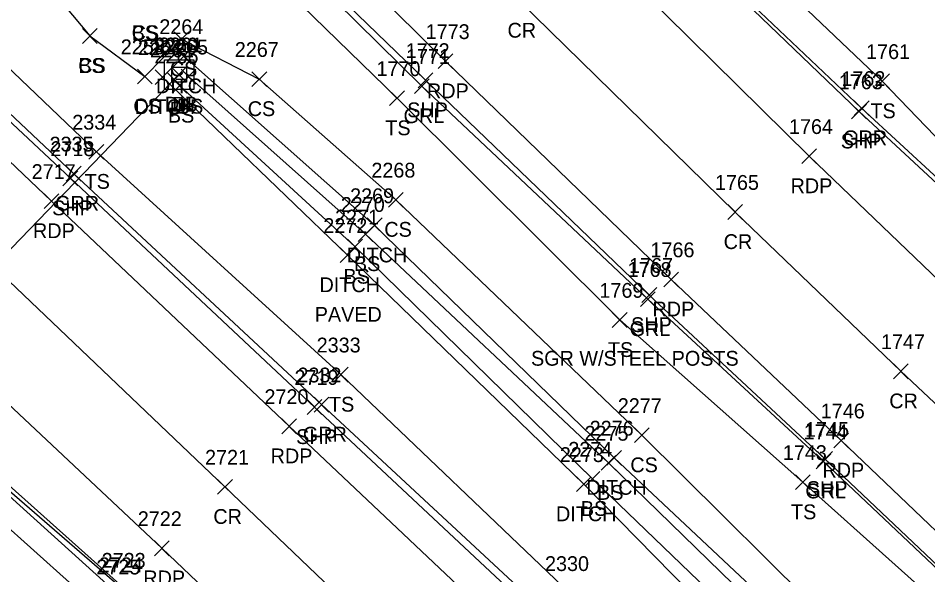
# Model space of a CAD drawing. Extents: x 1647574 to 1652703, y 212895 to 228670.
# Drawn here: x 1648547.8 to 1648670.8, y 227486.1 to 227561.3 of the extents above; entities that cross this region are included whole.
import ezdxf

# ---------------------------------------------------------------- set-up
doc = ezdxf.new("R2010")
doc.units = 0
for name, color, linetype in [('D_A', 7, 'Continuous'), ('D_C', 7, 'Continuous'), ('D_I', 7, 'Continuous'), ('D_TIC', 7, 'Continuous'), ('DCP', 7, 'Continuous'), ('DD', 7, 'Continuous'), ('DS', 7, 'Continuous'), ('L_A', 7, 'Continuous'), ('L_I', 7, 'Continuous'), ('L_TIC', 7, 'Continuous'), ('LELB', 7, 'Continuous'), ('P_A', 7, 'Continuous'), ('P_I', 7, 'Continuous'), ('P_TIC', 7, 'Continuous'), ('PET', 7, 'Continuous'), ('PRC', 7, 'Continuous'), ('PSP', 7, 'Continuous'), ('R_A', 7, 'Continuous'), ('R_C', 7, 'Continuous'), ('R_I', 7, 'Continuous'), ('R_TIC', 7, 'Continuous'), ('RC', 7, 'Continuous'), ('RGR', 7, 'Continuous')]:
    doc.layers.add(name, color=color, linetype=linetype)

msp = doc.modelspace()

# ---------------------------------------------------------------- linework, layer by layer
at = {"layer": 'D_TIC'}
for points in [[(1648569.22, 227555.15), (1648571.22, 227557.15)], [(1648571.22, 227555.15), (1648569.22, 227557.15)], [(1648566.35, 227552.33), (1648568.35, 227554.33)], [(1648568.35, 227552.33), (1648566.35, 227554.33)], [(1648566.35, 227552.33), (1648568.35, 227554.33)], [(1648568.35, 227552.33), (1648566.35, 227554.33)], [(1648568.57, 227552.68), (1648570.57, 227554.68)], [(1648570.57, 227552.68), (1648568.57, 227554.68)], [(1648567.95, 227552.01), (1648569.95, 227554.01)], [(1648569.95, 227552.01), (1648567.95, 227554.01)], [(1648595.04, 227532.3), (1648597.04, 227534.3)], [(1648597.04, 227532.3), (1648595.04, 227534.3)], [(1648591.36, 227528.27), (1648593.36, 227530.27)], [(1648593.36, 227528.27), (1648591.36, 227530.27)], [(1648627.44, 227500.88), (1648629.44, 227502.88)], [(1648629.44, 227500.88), (1648627.44, 227502.88)], [(1648623.34, 227497.31), (1648625.34, 227499.31)], [(1648625.34, 227497.31), (1648623.34, 227499.31)]]:
    msp.add_lwpolyline(points, dxfattribs=at)
at = {"layer": 'DCP'}
msp.add_lwpolyline([(1648568.95, 227553.01), (1648531, 227513.75)], dxfattribs=at)
at = {"layer": 'DD'}
for points in [[(1648567.35, 227553.33), (1648570.22, 227556.15), (1648596.04, 227533.3), (1648628.44, 227501.88), (1648658.02, 227474.12), (1648679.67, 227455.41), (1648690.82, 227447.94), (1648713.45, 227432.44), (1648744.75, 227411.46), (1648774.42, 227388.82), (1648782.61, 227380), (1648760.63, 227395.22), (1648734.75, 227411.81), (1648707.17, 227430.08), (1648688.91, 227442.53), (1648686.08, 227443.55), (1648681.35, 227446.24), (1648682.93, 227440.96), (1648688.01, 227426.23), (1648692.45, 227411.09)], [(1648567.35, 227553.33), (1648592.36, 227529.27), (1648624.34, 227498.31), (1648653.08, 227469.04), (1648672.69, 227449.29), (1648678.63, 227437.2), (1648685.39, 227422.2), (1648683.98, 227419.76)]]:
    msp.add_lwpolyline(points, dxfattribs=at)
at = {"layer": 'DS'}
for p, q in [((1648567.61, 227555.67), (1648571.61, 227555.67)), ((1648567.61, 227551.67), (1648567.61, 227555.67)), ((1648571.61, 227555.67), (1648571.61, 227551.67)), ((1648568.61, 227552.67), (1648568.61, 227554.67)), ((1648568.61, 227554.67), (1648570.61, 227554.67)), ((1648570.61, 227554.67), (1648570.61, 227552.67)), ((1648569.61, 227553.67), (1648569.61, 227553.67)), ((1648569.61, 227553.67), (1648569.61, 227553.67)), ((1648570.61, 227552.67), (1648568.61, 227552.67)), ((1648571.61, 227551.67), (1648567.61, 227551.67))]:
    msp.add_line(p, q, dxfattribs=at)
at = {"layer": 'L_TIC'}
for points in [[(1648556.52, 227557.9), (1648558.52, 227559.9)], [(1648558.52, 227557.9), (1648556.52, 227559.9)], [(1648556.52, 227557.9), (1648558.52, 227559.9)], [(1648558.52, 227557.9), (1648556.52, 227559.9)], [(1648568.91, 227557.45), (1648570.91, 227559.45)], [(1648570.91, 227557.45), (1648568.91, 227559.45)], [(1648563.97, 227552.43), (1648565.97, 227554.43)], [(1648565.97, 227552.43), (1648563.97, 227554.43)], [(1648569.86, 227552.4), (1648571.86, 227554.4)], [(1648571.86, 227552.4), (1648569.86, 227554.4)], [(1648569.86, 227552.4), (1648571.86, 227554.4)], [(1648571.86, 227552.4), (1648569.86, 227554.4)], [(1648568.64, 227551.19), (1648570.64, 227553.19)], [(1648570.64, 227551.19), (1648568.64, 227553.19)], [(1648579.44, 227552.07), (1648581.44, 227554.07)], [(1648581.44, 227552.07), (1648579.44, 227554.07)], [(1648663.68, 227551.78), (1648665.68, 227553.78)], [(1648665.68, 227551.78), (1648663.68, 227553.78)], [(1648598.07, 227549.48), (1648600.07, 227551.48)], [(1648600.07, 227549.48), (1648598.07, 227551.48)], [(1648557.41, 227542.24), (1648559.41, 227544.24)], [(1648559.41, 227542.24), (1648557.41, 227544.24)], [(1648597.91, 227535.76), (1648599.91, 227537.76)], [(1648599.91, 227535.76), (1648597.91, 227537.76)], [(1648593.8, 227531.12), (1648595.8, 227533.12)], [(1648595.8, 227531.12), (1648593.8, 227533.12)], [(1648592.38, 227529.42), (1648594.38, 227531.42)], [(1648594.38, 227529.42), (1648592.38, 227531.42)], [(1648628.18, 227519.51), (1648630.18, 227521.51)], [(1648630.18, 227519.51), (1648628.18, 227521.51)], [(1648590.46, 227512.12), (1648592.46, 227514.12)], [(1648592.46, 227512.12), (1648590.46, 227514.12)], [(1648631.18, 227503.93), (1648633.18, 227505.93)], [(1648633.18, 227503.93), (1648631.18, 227505.93)], [(1648626.68, 227500.2), (1648628.68, 227502.2)], [(1648628.68, 227500.2), (1648626.68, 227502.2)], [(1648624.49, 227498.03), (1648626.49, 227500.03)], [(1648626.49, 227498.03), (1648624.49, 227500.03)], [(1648652.94, 227497.58), (1648654.94, 227499.58)], [(1648654.94, 227497.58), (1648652.94, 227499.58)]]:
    msp.add_lwpolyline(points, dxfattribs=at)
at = {"layer": 'LELB'}
for points in [[(1648003.1, 228082.75), (1648021.4, 228065.95), (1648044.73, 228045.59), (1648079.17, 228018.19), (1648101.81, 227996.84), (1648138.98, 227971.46), (1648165.99, 227945.56), (1648168.81, 227943.47), (1648170.35, 227941.98), (1648172.46, 227939.54), (1648204.47, 227916.76), (1648236.47, 227884.75), (1648262.27, 227857.29), (1648293.8, 227821.06), (1648324.53, 227790.88), (1648359.53, 227760.77), (1648386.88, 227728.2), (1648427.75, 227689.04), (1648461.36, 227653.83), (1648490.92, 227628.14), (1648517.86, 227599.3), (1648549.31, 227568.74), (1648557.52, 227558.9)], [(1648859.74, 227356.65), (1648840.12, 227378.91), (1648802.29, 227415.99), (1648770.94, 227445.62), (1648740.28, 227477.01), (1648708.8, 227506.87), (1648686.01, 227530.68), (1648664.68, 227552.78), (1648630.72, 227585.09), (1648595.33, 227619.93), (1648569.85, 227644.46), (1648530.91, 227681.62), (1648503.48, 227711.09), (1648474.08, 227742.1), (1648442.94, 227774.58), (1648417.61, 227803.67), (1648387.3, 227839.86), (1648354.19, 227879.71), (1648321.73, 227919.78)], [(1648774.58, 227389.56), (1648743.29, 227416.76), (1648711.06, 227445.83), (1648678.9, 227476.26), (1648653.94, 227498.58), (1648629.18, 227520.51), (1648599.07, 227550.48), (1648561.98, 227586.59), (1648537.34, 227611.83), (1648495.7, 227652.57), (1648469.81, 227680.64), (1648438.58, 227713.56), (1648409.77, 227744.99), (1648382.96, 227775.49), (1648351.84, 227812.3), (1648319.03, 227851.85)], [(1648685.39, 227422.2), (1648676.45, 227434.08), (1648654, 227457.48), (1648622.43, 227483.58), (1648591.46, 227513.12), (1648558.41, 227543.24), (1648525.7, 227574.49), (1648490.45, 227607.71), (1648459.18, 227639.73), (1648423.29, 227671.04), (1648396.89, 227698.59), (1648372.2, 227720.93), (1648349.64, 227747.39), (1648318.23, 227770.21)], [(1648324.38, 227700.33), (1648355.95, 227670.04), (1648394.92, 227634.14), (1648428.77, 227603.61), (1648465.67, 227570.17), (1648497.97, 227538.04), (1648525.78, 227510.98), (1648559.61, 227480.7), (1648593.98, 227451.63), (1648632.72, 227416.53), (1648638.02, 227413.49)], [(1648557.52, 227558.9), (1648564.97, 227553.43), (1648569.91, 227558.45), (1648580.44, 227553.07), (1648598.91, 227536.76), (1648632.18, 227504.93), (1648659.98, 227477.37), (1648684.6, 227459.15), (1648697.58, 227453.74)], [(1648570.86, 227553.4), (1648569.64, 227552.19), (1648593.38, 227530.42), (1648625.49, 227499.03), (1648654.22, 227471.4), (1648675.13, 227451.27), (1648677.2, 227452.71), (1648687.88, 227445.25), (1648711.27, 227429.65), (1648742.96, 227408.64)], [(1648570.86, 227553.4), (1648594.8, 227532.12), (1648627.68, 227501.2), (1648656.32, 227473.31), (1648678.08, 227454.03), (1648689.55, 227446.73), (1648712.67, 227431.2), (1648742.96, 227408.64), (1648773.62, 227388.35)]]:
    msp.add_lwpolyline(points, dxfattribs=at)
at = {"layer": 'P_TIC'}
for points in [[(1648604.63, 227554.48), (1648606.63, 227556.48)], [(1648606.63, 227554.48), (1648604.63, 227556.48)], [(1648601.92, 227551.91), (1648603.92, 227553.91)], [(1648603.92, 227551.91), (1648601.92, 227553.91)], [(1648660.55, 227547.7), (1648662.55, 227549.7)], [(1648662.55, 227547.7), (1648660.55, 227549.7)], [(1648653.81, 227541.65), (1648655.81, 227543.65)], [(1648655.81, 227541.65), (1648653.81, 227543.65)], [(1648553.89, 227538.66), (1648555.89, 227540.66)], [(1648555.89, 227538.66), (1648553.89, 227540.66)], [(1648551.35, 227535.57), (1648553.35, 227537.57)], [(1648553.35, 227535.57), (1648551.35, 227537.57)], [(1648643.8, 227534.1), (1648645.8, 227536.1)], [(1648645.8, 227534.1), (1648643.8, 227536.1)], [(1648635.13, 227524.99), (1648637.13, 227526.99)], [(1648637.13, 227524.99), (1648635.13, 227526.99)], [(1648632.18, 227522.88), (1648634.18, 227524.88)], [(1648634.18, 227522.88), (1648632.18, 227524.88)], [(1648666.2, 227512.57), (1648668.2, 227514.57)], [(1648668.2, 227512.57), (1648666.2, 227514.57)], [(1648586.9, 227507.74), (1648588.9, 227509.74)], [(1648588.9, 227507.74), (1648586.9, 227509.74)], [(1648583.49, 227505.14), (1648585.49, 227507.14)], [(1648585.49, 227505.14), (1648583.49, 227507.14)], [(1648658.12, 227503.21), (1648660.12, 227505.21)], [(1648660.12, 227503.21), (1648658.12, 227505.21)], [(1648655.94, 227500.72), (1648657.94, 227502.72)], [(1648657.94, 227500.72), (1648655.94, 227502.72)], [(1648574.8, 227496.95), (1648576.8, 227498.95)], [(1648576.8, 227496.95), (1648574.8, 227498.95)], [(1648566.27, 227488.65), (1648568.27, 227490.65)], [(1648568.27, 227488.65), (1648566.27, 227490.65)]]:
    msp.add_lwpolyline(points, dxfattribs=at)
at = {"layer": 'PET'}
for points in [[(1648859.77, 227350.01), (1648834.8, 227373.42), (1648794.62, 227411.18), (1648764.14, 227439.93), (1648732.84, 227469.15), (1648700.82, 227498.96), (1648676.82, 227521.55), (1648654.81, 227542.65), (1648622.51, 227574.49), (1648586.27, 227609.85), (1648560.73, 227634.92), (1648521.71, 227673.76), (1648494.06, 227702.04), (1648464.63, 227733.46), (1648434.45, 227766.66), (1648408.12, 227796.3), (1648377.39, 227832.24), (1648343.92, 227872.68), (1648312.18, 227912.42)], [(1648813.95, 227358.94), (1648778.04, 227392.69), (1648747.29, 227421.36), (1648716.15, 227450.61), (1648683.9, 227480.61), (1648659.12, 227504.21), (1648636.13, 227525.99), (1648605.63, 227555.48), (1648567.94, 227592.71), (1648543.86, 227616.05), (1648502.53, 227657.19), (1648475.06, 227685.79), (1648444.59, 227717.74), (1648415.43, 227749.69), (1648388.57, 227780.05), (1648357.18, 227817.31), (1648324.35, 227856.66)], [(1648315.17, 227761.11), (1648349.65, 227728.18), (1648382.59, 227697.15), (1648419.4, 227663.05), (1648452.03, 227631.59), (1648489.19, 227596.81), (1648522.7, 227564.84), (1648552.35, 227536.57), (1648584.49, 227506.14), (1648616.97, 227475.48), (1648654.44, 227439.35), (1648683.93, 227411.58), (1648698.74, 227397.7)], [(1648333.95, 227709.46), (1648364.72, 227680.29), (1648403.35, 227644.3), (1648435.48, 227613.74), (1648473.57, 227577.89), (1648505.93, 227547.55), (1648536.04, 227518.97), (1648567.27, 227489.65), (1648600.56, 227457.93), (1648638.16, 227422.42), (1648655.14, 227406.15)]]:
    msp.add_lwpolyline(points, dxfattribs=at)
at = {"layer": 'PRC'}
for points in [[(1648838.07, 227353.54), (1648807.35, 227381.57), (1648786.43, 227402.05), (1648755.91, 227430.19), (1648724.74, 227459.82), (1648692.84, 227489.5), (1648667.2, 227513.57), (1648644.8, 227535.1), (1648615.58, 227563.67), (1648577.2, 227600.82), (1648552.11, 227624.84), (1648512.09, 227665.31), (1648484.94, 227693.32), (1648454.59, 227725.67), (1648425.77, 227757.32), (1648398.45, 227788.16), (1648367.06, 227824.4), (1648333.96, 227865.19)], [(1648306.81, 227751.95), (1648341.75, 227719.26), (1648373.8, 227688.7), (1648411.12, 227653.45), (1648443.57, 227623.29), (1648480.79, 227587.8), (1648514.61, 227556.06), (1648544.62, 227527.6), (1648575.8, 227497.95), (1648607.75, 227467.4), (1648646, 227431.31), (1648676.13, 227401.91)]]:
    msp.add_lwpolyline(points, dxfattribs=at)
at = {"layer": 'PSP'}
for points in [[(1648862.79, 227349.77), (1648858.81, 227353.71), (1648837.2, 227376.43), (1648798.17, 227413.97), (1648737.5, 227474.33), (1648707.27, 227504.55), (1648683.25, 227528.38), (1648680.78, 227530.89), (1648661.55, 227548.7), (1648627.48, 227581.41), (1648592.06, 227615.76), (1648566.89, 227641.29), (1648529.07, 227680.17), (1648501.07, 227708.87), (1648471.98, 227739.97), (1648441.35, 227773.22), (1648415.73, 227802.3), (1648385.43, 227838.08), (1648352.03, 227878.52), (1648319.68, 227918.25)], [(1648862.79, 227349.77), (1648859.77, 227350.01), (1648838.07, 227353.54), (1648813.95, 227358.94), (1648808.77, 227359.65), (1648801.07, 227367.02), (1648799.4, 227367.69), (1648775.51, 227390.23), (1648744.84, 227418.75), (1648714.06, 227447.93), (1648681.62, 227478.36), (1648656.94, 227501.72), (1648633.18, 227523.88), (1648602.92, 227552.91), (1648564.87, 227589.71), (1648540.52, 227613.53), (1648499.1, 227654.74), (1648471.89, 227682.44), (1648441.11, 227715.05), (1648412.29, 227746.76), (1648385.5, 227777.34), (1648354.02, 227814.19), (1648321.06, 227853.92)], [(1648318.36, 227763.01), (1648352.65, 227731.11), (1648385.57, 227699.76), (1648421.79, 227665.61), (1648455.44, 227633.9), (1648491.74, 227599.36), (1648525.61, 227567.1), (1648554.89, 227539.66), (1648587.9, 227508.74), (1648620.04, 227478.68), (1648657.86, 227443.1), (1648687.13, 227414.42), (1648699.8, 227401.85), (1648705.85, 227396.15)], [(1648327.45, 227702.95), (1648358.86, 227673.86), (1648397.53, 227637.26), (1648430.07, 227606.71), (1648467.1, 227572.24), (1648500.44, 227540.82), (1648528.21, 227514.54), (1648562.38, 227484.02), (1648596.57, 227454.64), (1648636.31, 227420.28), (1648642.1, 227415.21), (1648651.08, 227406.8), (1648655.14, 227406.15), (1648676.13, 227401.91), (1648698.74, 227397.7), (1648705.85, 227396.15)]]:
    msp.add_lwpolyline(points, dxfattribs=at)
at = {"layer": 'R_TIC'}
for points in [[(1648601.41, 227551.12), (1648603.41, 227553.12)], [(1648603.41, 227551.12), (1648601.41, 227553.12)], [(1648660.9, 227548.13), (1648662.9, 227550.13)], [(1648662.9, 227548.13), (1648660.9, 227550.13)], [(1648554.34, 227539.28), (1648556.34, 227541.28)], [(1648556.34, 227539.28), (1648554.34, 227541.28)], [(1648631.98, 227522.33), (1648633.98, 227524.33)], [(1648633.98, 227522.33), (1648631.98, 227524.33)], [(1648587.86, 227508.07), (1648589.86, 227510.07)], [(1648589.86, 227508.07), (1648587.86, 227510.07)], [(1648655.75, 227500.4), (1648657.75, 227502.4)], [(1648657.75, 227500.4), (1648655.75, 227502.4)]]:
    msp.add_lwpolyline(points, dxfattribs=at)
at = {"layer": 'RC'}
msp.add_lwpolyline([(1648527.38, 227514.07), (1648596.32, 227454.39), (1648636.06, 227420.08), (1648641.29, 227415.63)], dxfattribs=at)
at = {"layer": 'RGR'}
for points in [[(1648799.4, 227367.69), (1648775.21, 227390.09), (1648744.67, 227418.58), (1648713.63, 227447.71), (1648681.41, 227478.1), (1648656.75, 227501.4), (1648632.98, 227523.33), (1648602.41, 227552.12), (1648564.56, 227589.41), (1648540.3, 227613.5), (1648498.82, 227654.38), (1648471.44, 227682.07), (1648440.86, 227714.66), (1648411.81, 227746.44), (1648384.97, 227776.71), (1648353.62, 227813.75), (1648320.77, 227853.11)], [(1648697.72, 227405.66), (1648692.45, 227411.09), (1648683.98, 227419.76), (1648672.37, 227430.57), (1648663.53, 227439.76), (1648649.68, 227452.69), (1648619.08, 227481.01), (1648588.86, 227509.07), (1648555.34, 227540.28), (1648523.34, 227570.45), (1648487.38, 227604.54), (1648455.36, 227635), (1648420.16, 227668.08), (1648392.98, 227694.22), (1648369.01, 227717), (1648345.96, 227742.52)], [(1648327.16, 227702.7), (1648358.85, 227673.4), (1648397.37, 227637.01), (1648429.81, 227606.31), (1648466.78, 227571.83), (1648500.09, 227540.55), (1648527.38, 227514.07), (1648561.67, 227483.12), (1648595.98, 227454.16), (1648635.83, 227419.79), (1648639.15, 227416.04)], [(1648858.35, 227355.78), (1648837.72, 227376.91), (1648798.67, 227414.48), (1648769.05, 227444.38), (1648738.03, 227474.66), (1648707.59, 227505.32), (1648682.61, 227530.03), (1648661.9, 227549.13), (1648627.6, 227581.64), (1648592.63, 227616.36), (1648580.49, 227628.61)]]:
    msp.add_lwpolyline(points, dxfattribs=at)

# ---------------------------------------------------------------- texts
at = {"layer": 'D_A'}
for s, p in [('DITCH', (1648566.46, 227551.15)), ('DIB', (1648567.67, 227548.68)), ('DI', (1648568.67, 227548.67)), ('DITCH', (1648563.58, 227548.33)), ('DITCH', (1648563.58, 227548.33)), ('P', (1648568.33, 227548.01)), ('DITCH', (1648592.28, 227528.3)), ('DITCH', (1648588.59, 227524.27)), ('DITCH', (1648624.67, 227496.88)), ('DITCH', (1648620.57, 227493.31))]:
    msp.add_text(s, height=2, dxfattribs=at).set_placement(p)
at = {"layer": 'D_C'}
msp.add_text('PAVED', height=2, dxfattribs=at).set_placement((1648587.94, 227520.27))
at = {"layer": 'D_I'}
for s, p in [('2264', (1648566.92, 227559.15)), ('2263', (1648564.04, 227556.33)), ('2263', (1648564.04, 227556.33)), ('2262', (1648565.65, 227556.01)), ('2260', (1648566.22, 227556.67)), ('2261', (1648566.83, 227556.68)), ('2269', (1648592.72, 227536.3)), ('2272', (1648589.1, 227532.27)), ('2276', (1648625.12, 227504.88)), ('2273', (1648621.08, 227501.31))]:
    msp.add_text(s, height=2, dxfattribs=at).set_placement(p)
at = {"layer": 'L_A'}
for s, p in [('CS', (1648563.18, 227558.33)), ('BS', (1648563.18, 227558.33)), ('CS', (1648555.96, 227553.9)), ('BS', (1648555.96, 227553.9)), ('CS', (1648568.35, 227553.45)), ('CS', (1648563.41, 227548.43)), ('BS', (1648569.3, 227548.4)), ('BS', (1648569.3, 227548.4)), ('CS', (1648578.88, 227548.07)), ('TS', (1648663.09, 227547.78)), ('BS', (1648568.08, 227547.19)), ('TS', (1648597.48, 227545.48)), ('TS', (1648556.82, 227538.24)), ('CS', (1648597.35, 227531.76)), ('BS', (1648593.24, 227527.12)), ('BS', (1648591.82, 227525.42)), ('TS', (1648627.59, 227515.51)), ('TS', (1648589.87, 227508.12)), ('CS', (1648630.62, 227499.93)), ('BS', (1648626.12, 227496.2)), ('BS', (1648623.93, 227494.03)), ('TS', (1648652.35, 227493.58))]:
    msp.add_text(s, height=2, dxfattribs=at).set_placement(p)
at = {"layer": 'L_I'}
for s, p in [('2258', (1648561.71, 227556.43)), ('2265', (1648567.55, 227556.4)), ('2265', (1648567.55, 227556.4)), ('2267', (1648577.13, 227556.07)), ('2266', (1648566.27, 227555.19)), ('1761', (1648662.5, 227555.78)), ('1770', (1648596.29, 227553.48)), ('2334', (1648555.15, 227546.24)), ('2268', (1648595.6, 227539.76)), ('2270', (1648591.46, 227535.12)), ('2271', (1648590.69, 227533.42)), ('1769', (1648626.44, 227523.51)), ('2333', (1648588.2, 227516.12)), ('2277', (1648628.92, 227507.93)), ('2275', (1648624.42, 227504.2)), ('2274', (1648622.23, 227502.03)), ('1743', (1648651.24, 227501.58)), ('2330', (1648619.08, 227486.58))]:
    msp.add_text(s, height=2, dxfattribs=at).set_placement(p)
at = {"layer": 'P_A'}
for s, p in [('CR', (1648614.01, 227558.67)), ('RDP', (1648603.12, 227550.48)), ('SHP', (1648600.45, 227547.91)), ('SHP', (1648659.08, 227543.7)), ('RDP', (1648652.29, 227537.65)), ('SHP', (1648552.43, 227534.66)), ('RDP', (1648549.84, 227531.57)), ('CR', (1648643.24, 227530.1)), ('RDP', (1648633.62, 227520.99)), ('SHP', (1648630.72, 227518.88)), ('CR', (1648665.64, 227508.57)), ('SHP', (1648585.43, 227503.74)), ('RDP', (1648581.98, 227501.14)), ('RDP', (1648656.6, 227499.21)), ('SHP', (1648654.48, 227496.72)), ('CR', (1648574.23, 227492.95)), ('RDP', (1648564.76, 227484.65))]:
    msp.add_text(s, height=2, dxfattribs=at).set_placement(p)
at = {"layer": 'P_I'}
for s, p in [('1773', (1648602.94, 227558.48)), ('1772', (1648600.23, 227555.91)), ('1763', (1648658.81, 227551.7)), ('1764', (1648652.07, 227545.65)), ('2718', (1648552.2, 227542.66)), ('2717', (1648549.66, 227539.57)), ('1765', (1648642.06, 227538.1)), ('1766', (1648633.34, 227528.99)), ('1767', (1648630.44, 227526.88)), ('1747', (1648664.51, 227516.57)), ('2719', (1648585.2, 227511.74)), ('2720', (1648581.14, 227509.14)), ('1746', (1648656.37, 227507.21)), ('1745', (1648654.25, 227504.72)), ('2721', (1648573.11, 227500.95)), ('2722', (1648564.01, 227492.65)), ('2723', (1648559.12, 227487.02))]:
    msp.add_text(s, height=2, dxfattribs=at).set_placement(p)
at = {"layer": 'R_A'}
for s, p in [('GRL', (1648599.95, 227547.12)), ('GRR', (1648659.39, 227544.13)), ('GRR', (1648552.83, 227535.28)), ('GRL', (1648630.52, 227518.33)), ('GRR', (1648586.34, 227504.07)), ('GRL', (1648654.29, 227496.4))]:
    msp.add_text(s, height=2, dxfattribs=at).set_placement(p)
at = {"layer": 'R_C'}
msp.add_text('SGR W/STEEL POSTS', height=2, dxfattribs=at).set_placement((1648617.19, 227514.33))
at = {"layer": 'R_I'}
for s, p in [('1771', (1648600.28, 227555.12)), ('1762', (1648659.16, 227552.13)), ('2335', (1648552.08, 227543.28)), ('1768', (1648630.24, 227526.33)), ('2332', (1648585.6, 227512.07)), ('1744', (1648654.05, 227504.4)), ('2725', (1648558.41, 227486.12)), ('2724', (1648558.74, 227486.42))]:
    msp.add_text(s, height=2, dxfattribs=at).set_placement(p)

doc.saveas('drawing.dxf')
